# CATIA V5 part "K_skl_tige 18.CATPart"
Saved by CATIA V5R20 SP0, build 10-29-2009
Part number: skl_tige 18
Publications: "longueur tige", "longueur axe pivot", "liaison 3/18 sur 18", "droite appui verin gauche", "Droite.1", "Droite.3", "Plan.-55"
Bounding box of the stored display mesh (mm): x -205 to -55, y -593.344 to -85, z 0 to 209.968
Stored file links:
  G:\Khaled_CFAO_2011\SIL\SIL_GR2\mdardier\Khaled\CAD_ThinkMOTION\K_skl_tige 18.CATPart
  G:\Khaled_CFAO_2011\SIL\SIL_GR2\mdardier\Khaled\CAD_ThinkMOTION\K_skl_ass_tandem.CATProduct
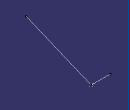
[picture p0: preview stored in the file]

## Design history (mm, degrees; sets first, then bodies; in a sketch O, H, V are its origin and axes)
External parameters (linked from other documents)
  `External.longueur tige` = 550 mm
  `External.longueur axe pivot` = 150 mm
Set1
  Point1 "liaison 3/18 sur 18": linked copy from another document
  Line1 "droite appui verin gauche": linked copy from another document
  Plane1 "Plan.-55": linked copy from another document
Set2
  Line2: type PtDir, RefPoint Point1, Direction Line1, Start 0, End 550 {= `External.longueur tige`}
  Line3: type Normal, RefPoint Point1, RefSkin Plane1, Start 0, End 150 {= `External.longueur axe pivot`}
Body1 (main body)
